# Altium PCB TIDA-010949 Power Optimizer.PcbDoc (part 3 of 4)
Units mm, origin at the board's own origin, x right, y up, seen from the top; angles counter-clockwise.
Board outline 129.4 x 84 mm, 4 copper layers (Power1, Ground1, Ground2, Power2), stack 1.926 mm thick; 265 components, 128 nets, 802 pads, 1069 vias.
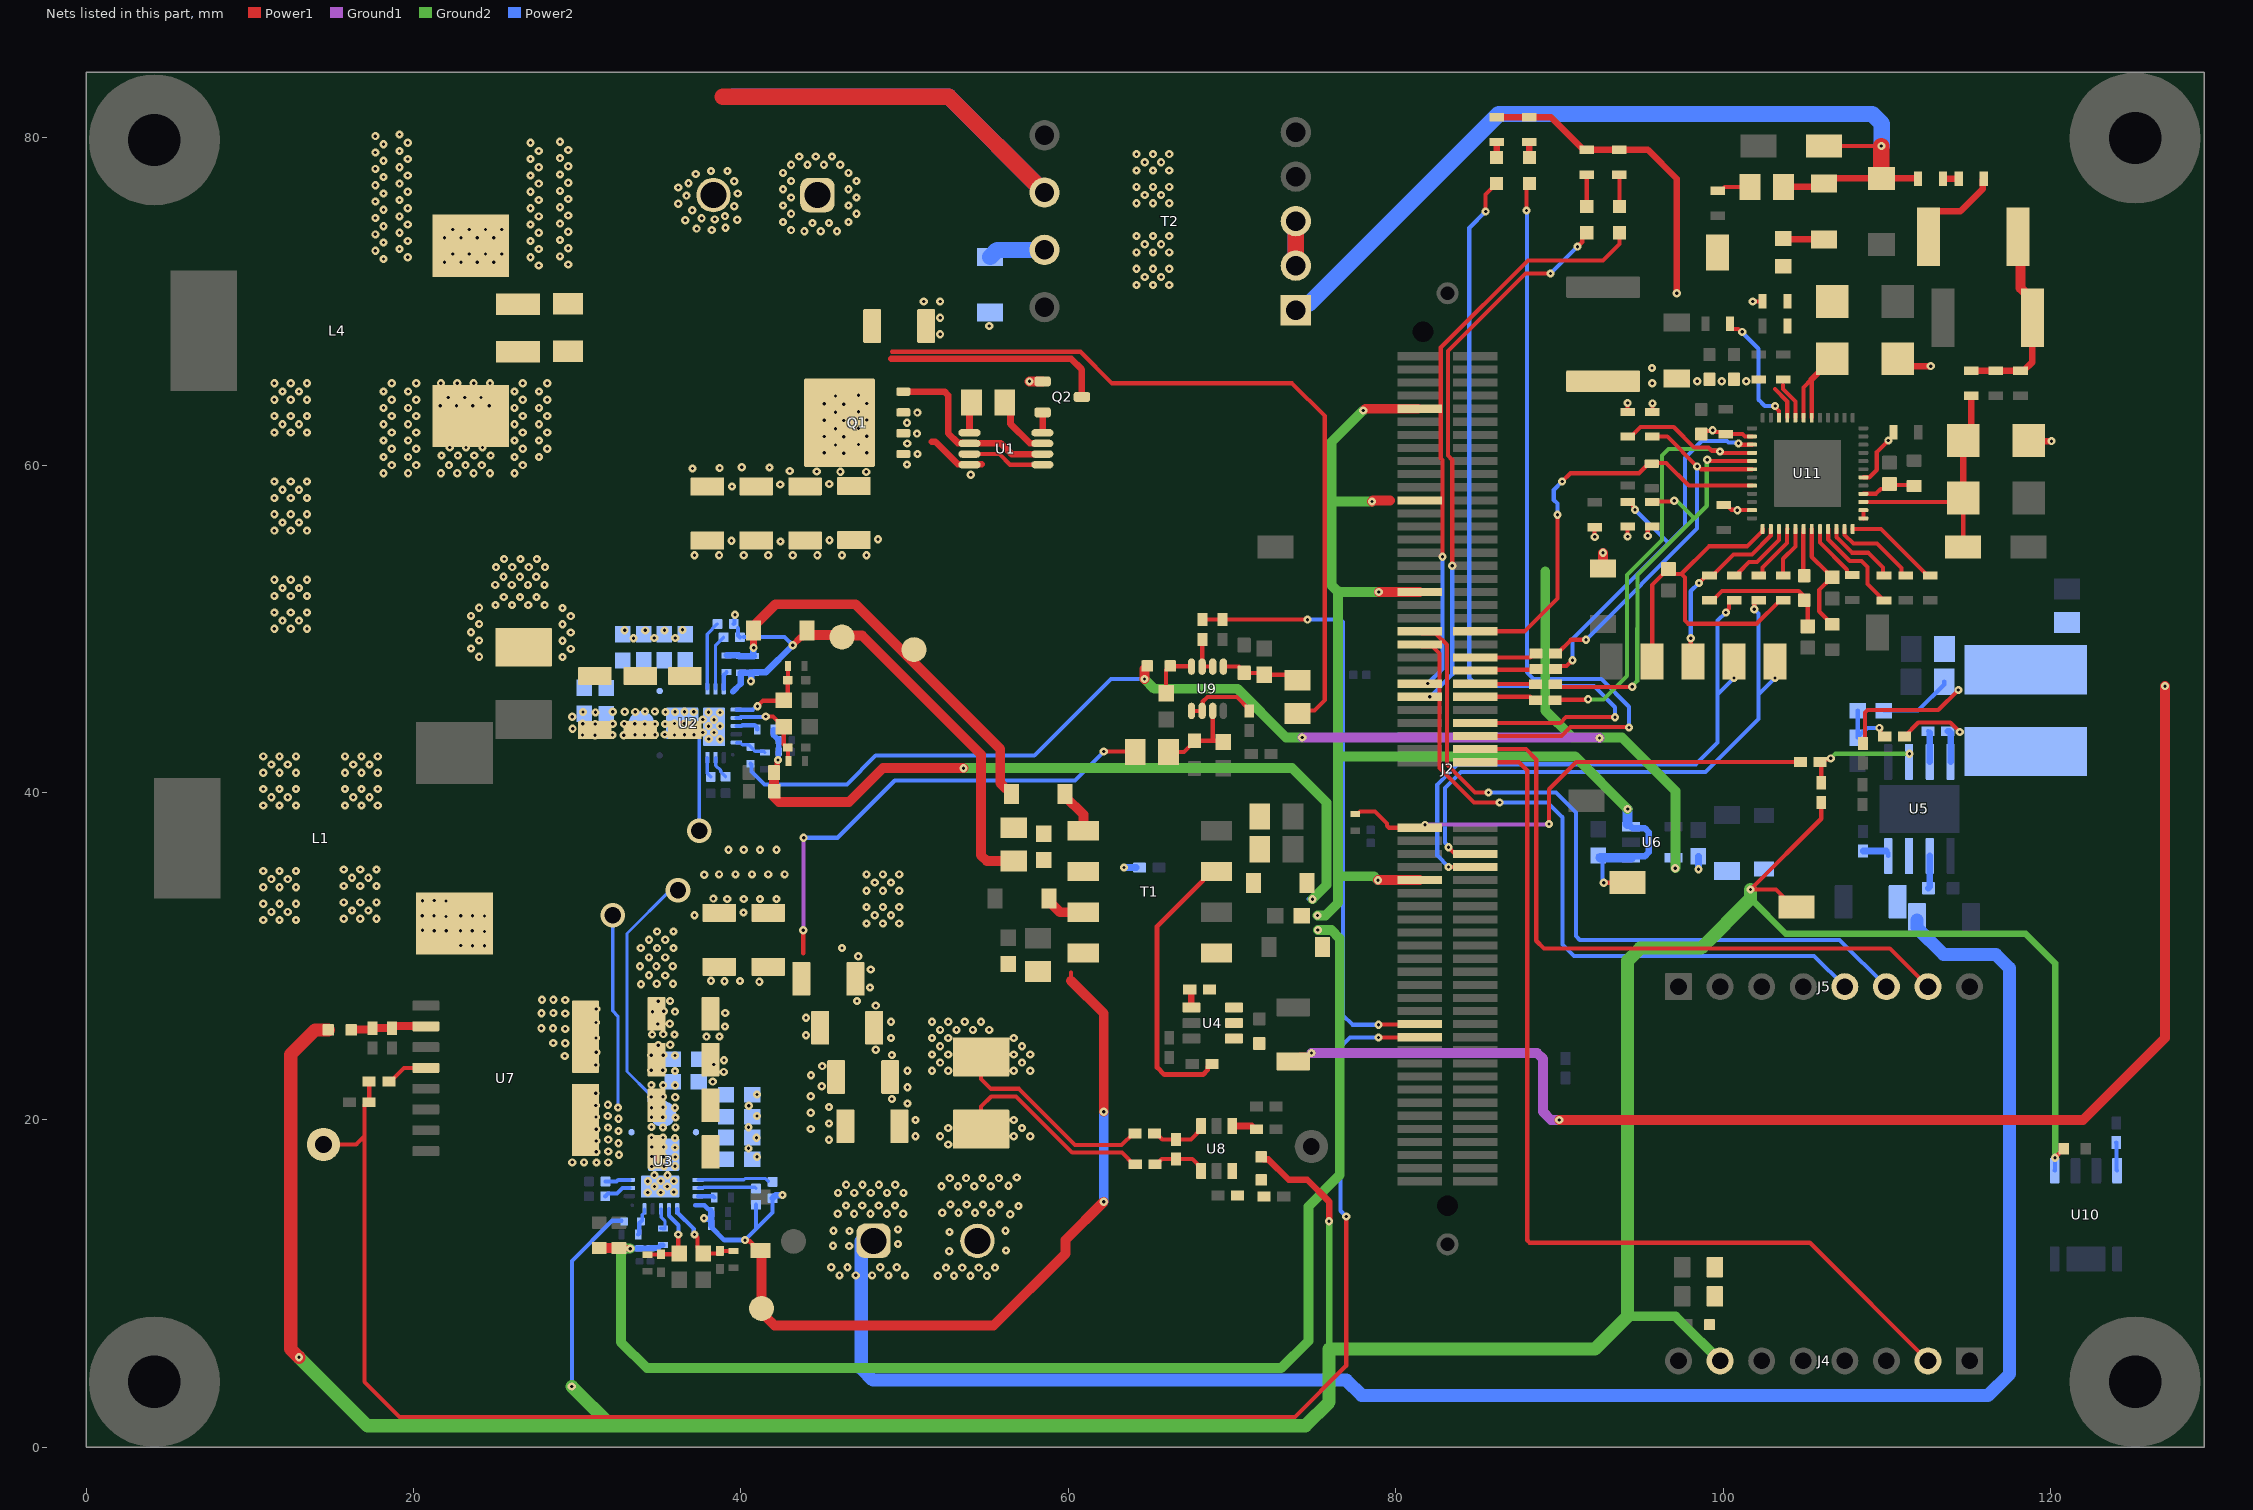
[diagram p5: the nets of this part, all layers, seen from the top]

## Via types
v1: diameter 0.5, hole 0.2, Power1 to Power2, tented both sides, 1061 vias
v2: diameter 1.5/1.5/1.5/1.5 (per signal layer), hole 1, Power1 to Power2, 4 vias
v3: diameter 3.508, hole 3.1, Power1 to Power2, tented both sides, 4 vias

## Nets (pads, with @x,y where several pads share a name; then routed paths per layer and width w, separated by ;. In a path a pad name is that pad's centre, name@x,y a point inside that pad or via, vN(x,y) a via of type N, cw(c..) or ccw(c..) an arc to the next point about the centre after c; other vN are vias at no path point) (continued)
ISO1_GND: C31.2 C44.1 C79.2 D2.2 pad.3 R16.1 R69.1 R71.1 T1.5 U3.11 | length 55.1
  Power1 w0.254: 60.174,28.5 60.174,29
  Power1 w0.3: v1@40.246,12.626 40.258,12.614 40.514,12.614 40.734,12.395 40.734,12.337 41.041,12.029 D2.2@41.194,12.029
  Power1 w0.6: D2.2@41.194,12.029 41.255,11.968 pad.3@41.255,8.498 ; pad.3@41.267,8.486 41.267,8.236 41.868,7.635 41.868,7.621 42.054,7.436 55.436,7.436 59.825,11.825 59.825,12.655 v1@62.17,15 ; 60.174,28.5 62.174,26.5 v1(62.174,20.5)
  Power2 w0.254: v1(37.749,13.987) v1@37.775,14.014 ; C31.2@38.015,14.541 38.129,14.541 38.192,14.478 C31.2@38.192,14.364 ; C79.2@38.192,13.455 C79.2@38.192,13.569 ; v1(40.246,12.654) 40.926,13.334 ; R71.1@40.926,14.816 40.926,13.334 ; R69.1@41.946,15.205 R69.1@41.937,15.214 41.937,14.345 40.926,13.334
  Power2 w0.3: U3.11@37.213,14.789 37.767,14.789 C31.2@38.015,14.541 ; C79.2@38.192,13.455 38.994,12.654 v1(40.246,12.654)
  Power2 w0.4: v1@37.775,13.961 38.192,13.961 ; C79.2@38.192,13.569 38.192,13.961 ; C31.2@38.192,14.364 38.192,13.961 ; R69.1@41.946,15.205 41.946,15.222 42.121,15.398 42.518,15.398 v1(42.539,15.418)
  Power2 w0.6: v1(62.174,15) v1(62.174,20.5)
ISO2_5V: C30.1 C45.2 C78.1 D1.1 D3.1 pad.5 R4.1 R17.2 | length 26
  Power1 w0.4: D3.1@40.728,49.914 40.771,49.871 40.771,48.853 v1(40.781,48.843)
  Power1 w0.6: D3.1@40.761,49.904 40.919,50.061 40.919,50.309 42.11,51.5 47,51.5 55.845,42.655 55.845,40.579 56.197,40.228 56.379,40.228 56.536,40.07 D1.1@56.536,39.918
  Power2 w0.254: C78.1@40.722,48.399 40.786,48.335 C78.1@40.794,48.335
  Power2 w0.4: R4.1@39.131,48.376 39.864,48.376 39.905,48.335 C30.1@40.001,48.335 C78.1@40.786,48.335 ; C78.1@40.722,48.399 40.76,48.437 40.76,48.823 v1(40.781,48.843)
ISO2_GND: C30.2 C45.1 C78.2 D3.2 pad.4 R17.1 R68.1 R70.1 T1.7 U2.11 | length 33.6
  Power1 w0.4: v1(43.174,49) 43.667,49.494 43.779,49.494 D3.2@44.036,49.751
  Power1 w0.6: D3.2@44.036,49.904 44.036,49.777 44.194,49.62 46.174,49.62 46.205,49.588 47.412,49.588 54.674,42.326 54.674,36.164 55.025,35.813 C45.1@56.675,35.813
  Power2 w0.254: R68.1@39.568,50.297 39.606,50.334 39.606,50.818 v1(39.643,50.855) ; R68.1@39.833,50.032 39.833,49.592 R70.1@39.942,49.483 ; R70.1@40.174,49.5 42.674,49.5 v1(43.174,49) ; v1(40.611,46.802) v1@40.66,46.85 ; C78.2@40.794,47.319 C78.2@40.81,47.335
  Power2 w0.35: U2.11@39.503,46.16 40.001,46.658
  Power2 w0.4: 40.001,46.658 C30.2@40.001,47.319 C78.2@40.794,47.319 40.741,47.319 40.731,47.31 40.731,47.256 40.632,47.157 40.632,46.834 v1@40.605,46.808 ; C78.2@40.81,47.335 41.509,47.335 v1(43.174,49)
LED1_EN: D15.1 J2.68 | length 34.1
  Power1 w0.254: J2.68@81.474,45.85 81.477,45.847 82.089,45.847 v1(82.093,45.843) ; v1(83.456,53.857) 83.456,60.332 83.19,60.597 83.19,66.97 87.925,71.705 v1(89.468,71.705) ; v1(91.113,73.35) 91.403,73.64 91.403,73.929 D15.1@91.674,74.2
  Power2 w0.254: v1(82.093,45.843) 83.456,47.206 v1(83.456,53.857) ; v1(89.468,71.705) v1(91.113,73.35) v1@91.124,73.35
LED2_EN: D16.1 J2.70 | length 35.7
  Power1 w0.254: J2.70@81.474,46.65 81.954,46.65 v1(81.964,46.66) ; v1(82.858,54.401) 82.858,60.315 82.756,60.417 82.756,67.178 88.078,72.5 92.674,72.5 93.674,73.5 D16.1@93.674,74.2
  Power2 w0.254: v1(81.964,46.66) 82.858,47.554 v1(82.858,54.401)
NetC1_1: C1.1 U1.7 | length 3.9
  Power1 w0.4: C1.1@56.125,63.825 56.473,63.476 56.473,62.52 57.657,61.337 58.407,61.337 U1.7@58.417,61.327
NetC1_2: C1.2 U1.1 | length 1.9
  Power1 w0.254: C1.2@53.967,63.699 C1.2@54.093,63.825
  Power1 w0.4: U1.1@53.967,61.977 C1.2@53.967,63.699
NetC32_2: C32.2 R8.1 R10.2 U2.12 | length 5.3
  Power1 w0.254: v1(41.019,45.268) 41.36,45.61 42.59,45.61 R10.2@42.615,45.635 42.865,45.885 C32.2@42.865,46.86 42.87,46.865 42.87,47.731 R8.1@42.874,47.735
  Power2 w0.254: U2.12@39.728,45.06 40.742,45.06 40.95,45.268 v1(41.019,45.268)
NetC33_2: C33.2 R9.1 R11.2 U3.12 | length 5.3
  Power1 w0.254: v1(37.174,13) 37.352,12.821 37.352,12.187 R11.2@37.7,11.839 38.723,11.839 38.723,11.862 38.85,11.99 R9.1@39.536,11.99
  Power2 w0.254: U3.12@36.113,14.564 36.113,14.343 37.125,13.331 37.125,13.049 v1(37.174,13)
NetC34_2: C34.2 R12.2 R14.1 U2.13 | length 5.4
  Power1 w0.254: v1(41.524,44.643) 41.972,44.643 42.242,44.373 42.242,44.358 42.59,44.01 R12.2@42.615,44.01 42.615,42.947 42.815,42.747 C34.2@42.865,42.747 42.886,42.726 42.886,41.956 R14.1@42.907,41.935
  Power2 w0.254: U2.13@39.728,44.56 39.949,44.56 39.995,44.606 41.487,44.606 v1(41.524,44.643)
NetC35_2: C35.2 R13.2 R15.1 U3.13 | length 5
  Power1 w0.254: R15.1@34.283,11.766 34.294,11.777 35.109,11.777 C35.2@35.12,11.789 36.175,11.789 R13.2@36.225,11.839 36.174,11.89 v1(36.174,13)
  Power2 w0.254: U3.13@35.613,14.564 35.615,14.562 35.615,14.146 36.195,13.566 36.195,13.021 v1(36.174,13)
NetC46_1: C46.1 T1.4 U4.6
NetC46_2: C46.2 U4.1 | length 1.1
  Power1 w0.254: C46.2@67.424,27.968 C46.2@67.524,27.868
  Power1 w0.4: U4.1@67.524,26.868 C46.2@67.524,27.868
NetC49_2: C49.2 C52.2 R18.2 | length 3.9
  Power1 w0.254: v1(109.552,43.95) 109.606,43.896 109.606,43.602 109.779,43.429 R18.2@109.879,43.429
  Power2 w0.254: C49.2@108.217,43.353 108.217,43.378 C49.2@108.23,43.392 ; C52.2@108.23,45.002 C49.2@108.23,43.392 ; v1(109.552,43.95) 108.813,43.95 108.59,43.726 108.565,43.726 C49.2@108.23,43.392
NetC50_1: C50.1 C51.1 D5.2 R20.2 T1.2 | length 17.6
  Power1 w0.254: T1.2@68.782,35.174 T1.2@69.053,35.174
  Power1 w0.3: R20.2@68.774,23.418 68.674,23.418 68.524,23.268 68.524,23.06 68.231,22.768 65.873,22.768 65.434,23.206 65.434,31.826 68.248,34.639 68.248,34.739 68.683,35.174 T1.2@68.782,35.174
NetC53_1: C53.1 L2.1 R18.1 U5.8 | length 6
  Power1 w0.254: R18.1@111.079,43.429 111.929,44.28 113.884,44.28 v1(114.466,43.698)
  Power2 w0.4: C53.1@113.729,43.747 113.805,43.747 113.905,43.647 U5.8@113.905,41.875
NetC53_2: C53.2 U5.7 | length 1.9
  Power2 w0.254: C53.2@112.529,43.747 C53.2@112.635,43.641
  Power2 w0.4: U5.7@112.635,41.875 C53.2@112.635,43.641
NetC65_1: C65.1 C66.1 FB1.2 U7.4 | length 4.6
  Power1 w0.5: FB1.2@16.215,25.515 17.45,25.515 17.5,25.565 C65.1@17.5,25.6 ; C65.1@17.515,25.615 C66.1@18.671,25.615 ; C66.1@18.686,25.6 18.686,25.68 18.736,25.73 U7.4@20.735,25.73
NetC67_1: C67.1 C68.1 FB2.2 U8.6
NetC71_1: C71.1 R34.2 U8.3 | length 3.4
  Power1 w0.254: R34.2@65.279,19.178 65.379,19.178 65.745,18.813 C71.1@66.584,18.813 67.499,18.813 68.114,19.427 U8.3@68.114,19.627
NetC71_2: C71.2 R37.2 U8.4 | length 3.4
  Power1 w0.254: R37.2@65.294,17.293 65.394,17.293 65.714,17.613 C71.2@66.584,17.613 67.579,17.613 68.114,17.077 U8.4@68.114,16.877
NetC73_1: C73.1 R40.1 R43.2 U9.3 | length 5.5
  Power1 w0.254: R40.1@66.129,42.48 67.077,42.48 67.711,43.114 R43.2@67.711,43.164 68.754,43.164 ; U9.3@68.829,44.989 68.829,43.239 68.754,43.164 ; C73.1@69.479,43.09 69.405,43.164 68.754,43.164
NetC75_1: C75.1 R41.1 R45.2 U9.5 | length 4.9
  Power1 w0.254: U9.5@69.479,47.689 70.422,47.689 70.749,47.362 R45.2@70.749,47.312 71.862,47.312 C75.1@71.974,47.2 73.659,47.2 R41.1@74.004,46.855
NetC77_2: C77.2 FB3.2 U9.8 | length 3.1
  Power1 w0.254: C77.2@65.982,46.062 65.982,47.482 66.116,47.615 FB3.2@66.316,47.615 ; FB3.2@66.232,47.731 66.253,47.71 67.507,47.71 U9.8@67.529,47.689
NetC81_1: C81.1 D10.2 R56.2 R58.2 T2.1 TP26.1 | length 56.3
  Power1 w0.254: C81.1@105.974,77 C81.1@106.174,77.2 C81.1@106.489,77.515 ; TP26.1@106.174,79.5 v1(109.674,79.5) ; R58.2@111.897,77.515 R58.2@111.912,77.5
  Power1 w0.4: R56.2@103.69,77 C81.1@105.974,77 ; C81.1@106.489,77.515 D10.2@109.674,77.515 110.174,77.515 R58.2@111.897,77.515
  Power1 w1: D10.2@109.674,77.515 v1(109.674,79.5)
  Power2 w1: T2.1@73.902,69.463 74.327,69.888 74.735,69.888 86.298,81.451 109.112,81.451 109.698,80.865 v1@109.698,79.525
NetC81_2: C81.2 L3.2 | length 2.5
  Power1 w0.254: L3.2@103.674,73.85 L3.2@103.724,73.8
  Power1 w0.4: L3.2@103.724,73.8 C81.2@106.174,73.8
NetC82_2: C82.2 C83.2 R51.1 | length 8.1
  Power1 w0.254: R51.1@99.174,51.738 99.364,51.738 99.945,52.319 104.63,52.319 105.174,51.775 105.174,51.75 C83.2@105.174,50.15
NetC84_2: C84.2 T2.8 | length 3.5
  Power2 w1: C84.2@55.229,72.72 55.652,73.143 58.541,73.143 T2.8@58.552,73.153
NetC85_1: C85.1 U11.22 | length 4.6
  Power1 w0.254: U11.22@106.924,56.1 106.931,56.093 106.931,55.598 107.876,54.652 108.869,54.652 109.778,53.743 109.778,53.316 C85.1@109.837,53.257
NetC85_2: C85.2 U11.21 | length 6.2
  Power1 w0.254: U11.21@106.424,56.1 106.431,56.093 106.431,55.456 107.744,54.143 108.454,54.143 108.821,53.776 108.821,52.749 C85.2@109.837,51.733
NetC86_1: C86.1 C91.1 L5.1 L6.2 R59.2 | length 12.1
  Power1 w0.254: C91.1@118.174,65.762 C91.1@118.364,65.762
  Power1 w0.4: C86.1@115.174,65.762 R59.2@116.674,65.762 C91.1@118.174,65.762 ; C91.1@118.364,65.762 118.904,66.302 L6.2@118.904,69
  Power1 w0.6: L5.1@118.174,74.108 118.174,70.81 118.904,70.08 L6.2@118.904,69
NetC86_2: C86.2 D13.2 D14.1 TP28.1 U11.27 | length 15.6
  Power1 w0.254: U11.27@108.574,57.75 114.424,57.75 D14.1@114.674,58 TP28.1@114.674,55 ; D13.2@114.674,61.5 D13.2@115.174,62
  Power1 w0.4: D14.1@114.674,58 D13.2@114.674,61.5 ; D13.2@115.174,62 C86.2@115.174,64.238
NetC87_1: C87.1 R58.1 | length 1
  Power1 w0.4: R58.1@113.436,77.5 C87.1@114.412,77.5
NetC87_2: C87.2 L5.2 | length 5.7
  Power1 w0.4: L5.2@112.674,74.643 112.674,75.122 113.061,75.51 114.501,75.51 115.882,76.89 115.882,77.446 C87.2@115.936,77.5
  Power1 w0.6: L5.2@112.561,73.961 L5.2@112.561,74.643
NetC88_1: C88.1 R56.1 | length 2.1
  Power1 w0.254: C88.1@99.674,76.762 99.864,76.762 100.102,77 R56.1@101.658,77
NetC89_1: C89.1 U11.23 | length 5.3
  Power1 w0.254: U11.23@107.424,56.1 107.431,56.093 107.431,55.74 107.962,55.208 109.399,55.208 110.895,53.713 110.895,53.389 111.022,53.262 C89.1@111.174,53.262
NetC90_1: C90.1 U11.24 | length 5.9
  Power1 w0.254: U11.24@107.924,56.1 109.645,56.1 112.483,53.262 C90.1@112.674,53.262
NetC92_2: C92.2 C93.2 U11.19 | length 7
  Power1 w0.254: U11.19@105.424,56.1 105.424,54.4 106.351,53.473 106.351,53.448 C93.2@106.649,53.15 ; C92.2@106.674,50.275 105.876,51.073 105.876,52.377 C93.2@106.649,53.15 ; C93.2@106.674,53.15 C93.2@106.649,53.15
NetC94_2: C94.2 C95.2 U11.28 | length 3.4
  Power1 w0.254: U11.28@108.574,58.25 108.581,58.257 109.341,58.257 109.636,58.552 109.876,58.552 C95.2@110.174,58.85 110.236,58.787 111.611,58.787 C94.2@111.674,58.725
NetD1_2: D1.2 T1.8 | length 2.7
  Power1 w0.254: D1.2@59.811,39.765 D1.2@59.811,39.918
  Power1 w0.6: D1.2@59.811,39.765 60.923,38.654 T1.8@60.923,37.664
NetD4_2: D4.2 T1.6 | length 2.5
  Power1 w0.6: D4.2@58.811,33.518 58.811,33.365 59.493,32.684 T1.6@60.923,32.684
NetD7_1: D7.1 J2.63 | length 49.8
  Power1 w0.254: J2.63@84.874,44.25 90.06,44.25 90.415,44.604 v1(93.404,44.604) ; v1(85.5,75.5) 85.5,76.526 D7.1@86.174,77.2
  Power2 w0.254: v1(85.5,75.5) 84.496,74.496 84.496,47.001 84.998,46.5 92.116,46.5 93.404,45.211 v1(93.404,44.604)
NetD7_2: D7.2 R29.1 | length 0.9
  Power1 w0.4: D7.2@86.174,78.8 R29.1@86.174,79.738
NetD9_2: D9.2 D11.1 L3.1 R50.1 R52.2 TP25.1 U11.42 U11.43 | length 6.7
  Power1 w0.254: U11.43@104.924,62.9 104.924,64.75 105.424,65.25 U11.42@105.424,62.9
  Power1 w0.4: 105.424,65.25 D9.2@106.674,66.5
NetD12_1: D12.1 J2.61 | length 47.9
  Power1 w0.254: J2.61@84.874,43.45 90.144,43.45 90.694,44 94.229,44 v1(94.258,43.971) ; v1(87.993,75.562) 87.993,77.019 D12.1@88.174,77.2
  Power2 w0.254: v1(87.993,75.562) 88.016,75.538 88.016,47.346 88.428,46.934 92.566,46.934 94.258,45.242 v1(94.258,43.971)
NetD12_2: D12.2 R76.1 | length 0.9
  Power1 w0.4: D12.2@88.174,78.8 R76.1@88.174,79.738
NetD15_2: D15.2 R61.1 | length 1.9
  Power1 w0.254: D15.2@91.674,75.8 R61.1@91.674,77.738
NetD16_2: D16.2 R62.1 | length 1.9
  Power1 w0.254: D16.2@93.674,75.8 R62.1@93.674,77.738
NetJ2_67: J2.67 R24.2 | length 3.7
  Power1 w0.254: J2.67@84.874,45.85 88.22,45.85 88.434,45.636 R24.2@88.534,45.636
NetJ2_69: J2.69 R26.2 | length 3.7
  Power1 w0.254: J2.69@84.874,46.65 84.889,46.635 88.534,46.635 R26.2@88.549,46.619
NetJ2_71: J2.71 R27.2 | length 3.7
  Power1 w0.254: J2.71@84.874,47.45 84.924,47.501 88.519,47.501 R27.2@88.57,47.552
NetJ2_73: J2.73 R28.2 | length 3.8
  Power1 w0.254: J2.73@84.874,48.25 88.223,48.25 88.474,48.5 R28.2@88.574,48.5
NetQ1_4: Q1.4 U1.2 U1.6 | length 11.4
  Power1 w0.4: Q1.4@49.923,64.492 52.439,64.492 52.674,64.257 52.674,61.936 53.258,61.352 53.478,61.352 53.494,61.337 53.957,61.337 U1.2@53.967,61.327 55.885,61.327 56.535,60.677 U1.6@58.417,60.677
NetQ2_2: Q2.2 U1.8 | length 1.2
  Power1 w0.4: U1.8@58.417,61.977 58.434,61.994 Q2.2@58.434,63.218
NetR3_2: R3.2 U3.10 | length 1
  Power2 w0.254: U3.10@37.388,15.339 38.306,15.339 R3.2@38.378,15.267
NetR4_2: R4.2 U2.10 | length 1.1
  Power2 w0.254: U2.10@38.953,46.335 38.953,47.165 R4.2@39.131,47.343
NetR5_2: R5.2 U2.14 | length 1.5
  Power2 w0.254: U2.14@39.728,44.06 39.73,44.062 40.056,44.062 40.103,44.109 40.847,44.109 40.999,43.957 R5.2@40.999,43.843
NetR7_2: R7.2 U3.14 | length 1.6
  Power2 w0.2: R7.2@35.085,13.388 35.289,13.388 35.358,13.457 35.358,13.827 35.132,14.053 35.132,14.544 U3.14@35.113,14.564
  Power2 w0.254: R7.2@35.229,13.367 R7.2@35.344,13.367
NetR19_1: R19.1 R22.1 U5.6 | length 6.9
  Power1 w0.254: R19.1@105.937,41.86 106.11,42.033 106.464,42.033 106.518,42.087 v1(106.587,42.087) ; R22.1@106,40.6 R19.1@106,41.86
  Ground2 w0.254: v1(106.587,42.087) 106.873,42.373 v1(111.387,42.373)
NetR30_1: R30.1 U11.15 | length 4.4
  Power1 w0.254: R30.1@100.674,53.262 100.864,53.262 100.991,53.389 100.991,53.484 101.594,54.088 102.07,54.088 103.417,55.434 103.417,56.093 U11.15@103.424,56.1
NetR31_1: R31.1 U7.6 | length 2.6
  Power1 w0.254: R31.1@18.494,22.339 18.594,22.339 19.43,23.175 U7.6@20.75,23.175
NetR32_1: R32.1 U8.1 | length 1.6
  Power1 w0.4: U8.1@70.014,19.627 71.208,19.627 71.403,19.432 R32.1@71.503,19.432
NetR33_2: R33.2 U5.4 | length 1.8
  Power2 w0.254: U5.4@109.972,36.427 110.095,36.304 U5.4@110.095,36.125
  Power2 w0.4: R33.2@108.562,36.427 U5.4@109.972,36.427
NetR38_1: R38.1 U11.16 | length 3.6
  Power1 w0.254: R38.1@102.174,53.262 102.285,53.262 102.412,53.389 102.412,53.748 103.917,55.252 103.917,56.093 U11.16@103.924,56.1
NetR39_1: R39.1 U11.17 | length 3.1
  Power1 w0.254: R39.1@103.674,53.262 103.674,54.283 104.424,55.033 U11.17@104.424,56.1
NetR42_1: R42.1 U9.1 U9.2 | length 4.6
  Power1 w0.254: U9.1@67.529,44.989 U9.2@68.179,44.989 68.216,45.026 68.216,45.552 68.504,45.839 70.302,45.839 71.054,45.087 R42.1@71.054,44.987
NetR44_1: R44.1 U9.6 U9.7 | length 2.3
  Power1 w0.254: R44.1@68.204,49.36 68.191,49.348 68.191,47.701 U9.7@68.179,47.689 U9.6@68.829,47.689
NetR57_1: R57.1 U11.20 | length 3.7
  Power1 w0.254: U11.20@105.924,56.1 105.924,55.268 107.583,53.609 107.583,53.418 107.71,53.291 R57.1@107.9,53.291
NetR60_2: R60.2 U11.46 | length 7.6
  Power1 w0.254: R60.2@100.424,68.643 100.424,68.443 100.547,68.32 100.928,68.32 101.105,68.143 v1(101.174,68.143) ; v1(103.186,63.616) 103.186,63.547 103.417,63.316 103.417,62.907 U11.46@103.424,62.9
  Power2 w0.254: v1(101.174,68.143) 101.174,68.111 102.174,67.111 102.174,64 102.551,63.623 103.179,63.623 v1(103.186,63.616)
NetR63_2: R63.2 U10.4 | length 1.7
  Power2 w0.254: R63.2@124.02,18.611 124.049,18.582 124.049,16.929 U10.4@124.079,16.9
NetR64_2: R64.2 U2.3 | length 1.4
  Power2 w0.2: U2.3@38.453,42.135 38.47,42.117 38.47,41.644 38.764,41.35 38.764,41.267 R64.2@39.066,40.965
NetR65_2: R65.2 U3.3 | length 1.7
  Power2 w0.254: R65.2@31.718,15.339 31.88,15.5 32.441,15.5 32.778,15.837 33.186,15.837 U3.3@33.188,15.839
NetR66_2: R66.2 U2.4 | length 1.3
  Power2 w0.2: U2.4@37.953,42.135 37.953,41.168 R66.2@38.164,40.956
NetR67_2: R67.2 U3.4 | length 1.5
  Power2 w0.254: R67.2@31.727,16.235 32.408,16.235 32.509,16.337 33.186,16.337 U3.4@33.188,16.339
NetR68_2: R68.2 U2.8 | length 4.2
  Power2 w0.2: U2.8@37.953,46.335 37.953,49.681 R68.2@38.568,50.297
NetR69_2: R69.2 U3.8 | length 4.4
  Power2 w0.2: U3.8@37.397,16.348 40.187,16.348 40.255,16.416 41.51,16.416 R69.2@41.694,16.231
NetR70_2: R70.2 U2.9 | length 3.4
  Power2 w0.2: U2.9@38.453,46.335 38.453,48.994 R70.2@38.942,49.483
NetR71_2: R71.2 U3.9 | length 3.6
  Power2 w0.2: U3.9@37.388,15.839 37.413,15.864 37.717,15.864 37.736,15.882 40.859,15.882 R71.2@40.926,15.816
NetR72_1: R72.1 R73.2 U2.16 | length 2
  Power2 w0.2: U2.16@39.728,43.06 39.753,43.035 39.978,43.035 40.093,42.919 40.468,42.919 40.743,42.644 40.743,42.638 40.86,42.521 41.395,42.521 R73.2@41.474,42.443
NetR74_1: R74.1 R75.2 U3.16 | length 1.7
  Power2 w0.2: R74.1@33.975,13.832 33.975,14.201 34.113,14.339 U3.16@34.113,14.564
  Power2 w0.254: R75.2@33.728,12.999 33.791,13.062 33.791,13.691 R74.1@33.895,13.794
NetT2_2: T2.2 T2.3 | length 5.4
  Power1 w1: T2.2@73.902,72.183 T2.3@73.902,74.903
  Power2 w1: T2.2@73.902,72.183 T2.3@73.902,74.903
NetU1_3: U1.3 U1.5 | length 4.7
  Power1 w0.254: U1.3@53.967,60.677 55.79,60.677 56.44,60.027 U1.5@58.417,60.027
NetU11_25: U11.25 U11.26 | length 0.5
  Power1 w0.254: U11.25@108.574,56.75 U11.26@108.574,57.25
Output_I: C70.1 J2.24 R31.2 TP16.1 | length 108.1
  Power1 w0.254: TP16.1@14.5,18.5 16.5,18.5 17,19 ; C70.1@17.28,21.079 17.18,21.079 17.007,20.906 17.007,20.765 17,20.757 17,19 ; C70.1@17.294,21.092 R31.2@17.294,22.339 ; v1(76.98,14.095) 76.98,4.98 73.857,1.857 19.143,1.857 17,4 17,19 ; v1(78.955,25.035) 78.963,25.043 81.466,25.043 J2.24@81.474,25.05
  Power2 w0.254: v1(76.98,14.095) 76.625,14.45 76.625,24.451 77.209,25.035 v1(78.955,25.035)
Output_V: C76.1 J2.26 R44.2 | length 37.6
  Power1 w0.254: R44.2@68.204,50.56 C76.1@69.426,50.56 ; C76.1@69.427,50.561 v1(74.612,50.561) ; v1(78.948,25.816) 78.965,25.833 81.457,25.833 J2.26@81.474,25.85
  Power2 w0.254: v1(74.612,50.561) 76.635,50.561 76.784,50.412 76.784,26.39 77.357,25.816 v1(78.948,25.816)
PA_IN: C82.1 U11.18 | length 2.9
  Power1 w0.254: U11.18@104.924,56.1 104.917,56.093 104.917,55.872 104.907,55.862 104.907,53.3 C82.1@104.962,53.246
PGND: C2.1 C3.1 C4.1 C5.1 C6.1 C7.1 C8.1 C9.1 C10.1 C11.1 C12.1 C13.1 C14.1 C15.1 C16.1 C17.1 C18.1 C19.1 C20.1 C21.1 C22.1 C23.1 C24.1 C25.1 C26.1 C27.1 C28.1 C29.1 C60.1 C61.1 C69.1 C84.1 L4.1 Q1.1 Q1.2 Q1.3 Q2.1 R1.2 R2.2 R23.2 R34.1 U1.4 U2.6 U3.6 | length 38.8
  Power1 w0.254: R2.2@54.674,23.853 54.674,22.5 55.275,21.899 56.986,21.899 60.422,18.462 63.263,18.462 63.979,19.178 R34.1@64.079,19.178
  Power1 w0.4: 51.647,61.426 51.884,61.426 53.258,60.052 53.478,60.052 53.503,60.027 U1.4@53.967,60.027 ; U1.4@53.986,60.046 54.699,60.046
  Power1 w0.6: v1(57.63,65.118) Q2.1@58.434,65.118
  Power2 w0.2: v1@34.437,21.565 33.043,22.958 33.043,31.389 35.69,34.035 v2(36.159,34.035) ; v2(37.462,37.662) 37.462,43.5
  Power2 w0.254: 34.437,21.153 34.437,21.395 v1@34.437,21.565
  Power2 w0.4: v1(63.405,35.419) R1.2@64.155,35.419
  other v1: 34.31,15.569 35.108,15.569 35.907,15.59 35.501,15.93 34.727,15.938 34.318,16.253 35.905,16.26 35.11,16.274 34.714,16.625 35.518,16.621 34.554,17.155 35.298,17.163 35.981,17.168 35.269,17.754 35.984,17.741 40.99,17.754 34.555,17.768 40.466,18.263 35.979,18.313 35.274,18.341 34.55,18.345 35.975,18.895 35.237,18.927 40.96,18.908 34.546,18.931 50.674,19 34.541,19.564 35.242,19.541 36.007,19.545 40.471,19.554 50.674,20 36.007,20.145 34.537,20.168 35.233,20.168 40.983,20.232 34.541,20.736 35.979,20.745 35.248,20.766 40.48,20.868 50.174,21 49.225,21.272 35.988,21.384 34.53,21.395 35.248,21.42 40.983,21.551 50.174,22 35.251,22.123 35.984,22.115 34.532,22.139 35.977,22.991 50.174,23 51.674,23 52.674,23 56.674,23 57.674,23 34.52,23.035 35.233,23.03 52.174,23.5 57.174,23.5 34.53,23.948 35.253,23.958 35.974,23.934 49.225,23.972 51.674,24 52.674,24 56.674,24 57.674,24 48.244,24.282 52.174,24.5 57.174,24.5 34.952,24.569 35.683,24.588 49.174,25 51.674,25 52.674,25 56.674,25 34.58,25.221 35.949,25.221 35.263,25.24 52.174,25.5 53.174,25.5 54.174,25.5 55.174,25.5 34.927,25.856 35.658,25.875 49.174,26 51.674,26 52.674,26 53.674,26 54.674,26 34.601,26.615 35.97,26.615 35.284,26.634 48.244,26.982 34.947,27.25 35.679,27.27 47.095,27.266 47.889,28.092 33.9,28.287 34.861,28.318 35.861,28.318 35.381,28.82 34.382,28.839 47.934,29.193 33.839,29.384 34.839,29.384 35.839,29.384 34.386,29.929 35.386,29.929 47.174,30 33.886,30.504 34.886,30.504 35.886,30.504 46.174,30.5 34.386,31.004 35.386,31.004 34.886,31.504 35.886,31.504 47.674,32 48.674,32 49.674,32 10.818,32.21 11.818,32.21 12.818,32.21 15.744,32.291 16.744,32.291 17.744,32.291 37.174,32.5 48.174,32.5 49.174,32.5 40.167,32.674 11.318,32.71 12.318,32.71 16.244,32.791 17.244,32.791 47.674,33 48.674,33 49.674,33 10.818,33.21 11.818,33.21 12.818,33.21 15.744,33.291 16.744,33.291 17.744,33.291 39.174,33.5 40.174,33.5 41.174,33.5 42.174,33.5 38.32,33.517 47.674,34 48.674,34 49.674,34 10.818,34.21 11.818,34.21 12.818,34.21 15.744,34.291 16.744,34.291 17.744,34.291 48.174,34.5 49.174,34.5 11.318,34.71 12.318,34.71 16.244,34.791 17.244,34.791 37.764,34.972 38.674,35 39.674,35 40.674,35 41.674,35 42.674,35 47.674,35 48.674,35 49.674,35 10.818,35.21 11.818,35.21 12.818,35.21 15.744,35.291 16.744,35.291 17.744,35.291 40.174,36.5 41.174,36.5 42.174,36.5 39.248,36.507 10.818,39.21 11.818,39.21 12.818,39.21 15.818,39.21 16.818,39.21 17.818,39.21 11.318,39.71 12.318,39.71 16.318,39.71 17.318,39.71 10.818,40.21 11.818,40.21 12.818,40.21 15.818,40.21 16.818,40.21 17.818,40.21 10.818,41.21 11.818,41.21 12.818,41.21 15.818,41.21 16.818,41.21 17.818,41.21 11.318,41.71 12.318,41.71 16.318,41.71 17.318,41.71 10.818,42.21 11.818,42.21 12.818,42.21 15.818,42.21 16.818,42.21 17.818,42.21 38.722,43.258 38.039,43.265 31.093,43.499 32.152,43.508 32.84,43.503 34.109,43.515 30.328,43.52 33.533,43.529 34.753,43.525 35.349,43.54 35.939,43.519 36.55,43.522 37.132,43.529 37.666,43.661 38.353,43.674 29.722,43.899 38.017,44.057 38.722,44.056 30.333,44.2 31.109,44.181 32.169,44.198 32.871,44.195 33.525,44.195 34.123,44.18 34.751,44.189 35.364,44.185 35.951,44.221 36.537,44.217 37.128,44.245 38.362,44.448 37.67,44.465 29.703,44.63 31.118,44.898 38.024,44.907 38.724,44.889 30.357,44.921 32.177,44.931 32.907,44.935 33.546,44.927 35.396,44.922 35.978,44.927 36.551,44.931 37.124,44.928 34.146,44.954 34.746,44.954 33.44,49.42 34.708,49.447 35.989,49.436 32.898,49.916 34.154,49.906 35.33,49.906 36.437,49.937 11.5,50 12.5,50 13.5,50 12,50.5 13,50.5 11.5,51 12.5,51 13.5,51 11.5,52 12.5,52 13.5,52 12,52.5 13,52.5 11.5,53 12.5,53 13.5,53 37.174,54.5 38.674,54.5 40.174,54.5 41.674,54.5 43.174,54.5 44.674,54.5 46.174,54.5 47.674,54.5 42.416,55.34 39.433,55.383 45.413,55.412 48.381,55.47 11.5,56 12.5,56 13.5,56 12,56.5 13,56.5 11.5,57 12.5,57 13.5,57 11.5,58 12.5,58 13.5,58 12,58.5 13,58.5 11.5,59 12.5,59 13.5,59 54.039,59.414 18.174,59.5 19.674,59.5 21.674,59.5 22.674,59.5 23.674,59.5 24.674,59.5 26.174,59.5 18.674,60 20.174,60 22.174,60 23.174,60 24.174,60 26.674,60 50.153,60.037 18.174,60.5 19.674,60.5 26.174,60.5 27.674,60.5 21.712,60.585 22.712,60.585 23.712,60.585 24.712,60.585 50.792,60.675 18.674,61 20.174,61 26.674,61 28.174,61 22.212,61.085 23.212,61.085 24.212,61.085 50.162,61.316 18.174,61.5 19.674,61.5 26.174,61.5 27.674,61.5 50.762,61.926 11.5,62 12.5,62 13.5,62 18.674,62 20.174,62 26.674,62 28.174,62 12,62.5 13,62.5 18.174,62.5 19.674,62.5 26.174,62.5 27.674,62.5 50.153,62.587 11.5,63 12.5,63 13.5,63 18.674,63 20.174,63 26.674,63 28.174,63 50.782,63.207 18.174,63.5 19.674,63.5 26.174,63.5 27.674,63.5 21.627,63.629 22.627,63.629 23.627,63.629 24.627,63.629 11.5,64 12.5,64 13.5,64 18.674,64 20.174,64 26.674,64 28.174,64 22.127,64.129 23.127,64.129 24.127,64.129 12,64.5 13,64.5 18.174,64.5 19.674,64.5 26.174,64.5 27.674,64.5 11.5,65 12.5,65 13.5,65 18.674,65 20.174,65 21.674,65 22.674,65 23.674,65 24.674,65 26.674,65 28.174,65 52.174,68 55.174,68.5 52.174,69 51.174,70 52.174,70 64.174,71 65.174,71 66.174,71 64.674,71.5 65.674,71.5 64.174,72 65.174,72 66.174,72 64.174,73 65.174,73 66.174,73 64.674,73.5 65.674,73.5 64.174,74 65.174,74 66.174,74 64.174,76 65.174,76 66.174,76 64.674,76.5 65.674,76.5 64.174,77 65.174,77 66.174,77 64.174,78 65.174,78 66.174,78 64.674,78.5 65.674,78.5 64.174,79 65.174,79 66.174,79
PGOOD_5V: C112.1 J2.56 R19.2 | length 30.3
  Power1 w0.254: C112.1@77.534,38.681 77.648,38.681 77.816,38.849 78.739,38.849 79.477,38.111 79.477,37.973 79.6,37.85 J2.56@81.474,37.85 J2.56@81.449,37.874 ; v1(89.373,38.071) 89.373,40.199 91.035,41.86 R19.2@104.737,41.86
  Ground1 w0.254: v1(81.797,38.024) 81.82,38.047 89.35,38.047 v1(89.373,38.071)
PLC_HRPWM1: J2.49 R30.2 TP22.1 | length 35.8
  Power1 w0.254: v1(83.237,35.457) 83.244,35.45 J2.49@84.874,35.45 ; v1(100.174,51) 100.174,51.069 100.356,51.251 100.356,51.611 100.483,51.738 R30.2@100.674,51.738
  Power2 w0.254: v1(83.237,35.457) 82.547,36.147 82.547,40.48 83.797,41.73 98.351,41.73 99.674,43.053 99.674,46 ; v1(100.174,51) 99.674,50.5 99.674,46 ; v1(100.674,47) 99.674,46
PLC_HRPWM2: J2.51 R38.2 TP23.1 | length 35.4
  Power1 w0.254: v1(83.224,36.659) 83.634,36.25 J2.51@84.874,36.25 ; v1(101.912,51.198) 101.912,51.667 101.983,51.738 R38.2@102.174,51.738
  Power2 w0.254: v1(83.224,36.659) 83.224,36.722 83.015,36.931 83.015,40.28 83.986,41.25 98.924,41.25 102.174,44.5 102.174,46 ; v1(101.912,51.198) 102.174,50.937 102.174,46 ; v1(103.174,47) 102.174,46
PV_PGND: J1.2 R2.1 R37.1 | length 12.8
  Power1 w0.254: R2.1@54.674,19.433 54.674,20.812 55.295,21.433 56.81,21.433 60.24,18.002 63.285,18.002 63.994,17.293 R37.1@64.094,17.293
  other v1: 52.027,10.476 53.027,10.476 54.027,10.476 55.027,10.476 52.527,10.976 53.527,10.976 54.527,10.976 55.527,10.976 52.725,11.978 56.196,12.027 52.744,13.149 56.174,13.234 56.454,14.236 52.299,14.327 53.299,14.327 54.299,14.327 55.299,14.327 56.954,14.736 52.799,14.827 53.799,14.827 54.799,14.827 55.799,14.827 52.262,15.942 53.262,15.942 54.262,15.942 55.262,15.942 56.35,15.976 52.762,16.442 53.762,16.442 54.762,16.442 55.762,16.442 56.85,16.476 52.674,18.5 52.174,19 56.674,19 57.674,19 52.674,19.5 57.174,19.5 56.674,20
RSD_MCU: J2.59 J5.7 | length 40.1
  Power1 w0.254: J2.59@84.874,42.65 87.963,42.65 88.592,42.021 88.592,30.947 89.067,30.472 110.19,30.472 J5.7@112.524,28.138
RST_MCU: J2.57 J4.2 | length 60.1
  Power1 w0.254: J2.57@84.874,41.85 87.54,41.85 88.039,41.351 88.039,12.649 88.187,12.5 105.302,12.5 J4.2@112.893,4.909
SD_EN: J2.77 R54.2 U11.8 | length 25.9
  Power1 w0.254: J2.77@84.874,49.85 87.881,49.85 89.891,51.859 v1(89.891,56.975) ; v1(90.174,59) 90.679,59.505 94.866,59.505 95.445,60.085 R54.2@95.645,60.085 ; R54.2@95.645,60.127 96.53,60.127 97.907,58.75 U11.8@101.774,58.75
  Power2 w0.254: v1(89.891,56.975) 89.891,57.648 89.66,57.879 89.66,58.486 v1(90.174,59)
SPI_CLK: R27.1 R46.1 U11.3 | length 24.9
  Power1 w0.254: R27.1@89.77,47.552 89.943,47.725 90.444,47.725 v1(90.801,48.081) ; R46.1@94.174,57.75 94.374,57.75 94.497,57.627 94.497,57.474 94.624,57.347 v1(94.624,57.278) ; v1(100.953,61.331) 101.022,61.331 101.103,61.25 U11.3@101.774,61.25
  Power2 w0.254: v1(90.801,48.081) 90.801,49.37 96.698,55.267 ; v1@94.755,57.278 v1(94.624,57.278) 96.634,55.267 96.698,55.267 ; v1(100.953,61.331) 100.904,61.38 100.335,61.38 100.238,61.477 98.702,61.477 97.674,60.449 97.674,56.243 96.698,55.267
SPI_CS: R28.1 R49.1 U11.6 | length 22.5
  Power1 w0.254: R28.1@89.774,48.5 89.874,48.5 90.703,49.329 v1(91.625,49.329) ; R49.1@95.674,61.75 96.597,61.75 v1(98.42,59.927) ; v1@98.469,59.878 98.537,59.878 98.665,59.75 U11.6@101.774,59.75
  Power2 w0.254: v1(91.625,49.329) 98.42,56.124 v1(98.42,59.927)
SPI_SIMO: R24.1 R47.1 U11.4 | length 31.6
  Power1 w0.254: R24.1@89.734,45.636 89.763,45.665 91.731,45.665 v1(91.76,45.693) ; R47.1@94.174,61.75 94.374,61.75 94.951,62.327 96.989,62.327 98.239,61.077 99.109,61.077 99.309,60.877 99.774,60.877 99.871,60.78 99.949,60.78 99.979,60.75 U11.4@101.774,60.75
  Ground2 w0.254: v1(91.76,45.693) 92.695,45.693 94.133,47.132 94.133,53.281 96.273,55.421 96.273,60.6 96.666,60.992 99.213,60.992 99.328,60.877 99.774,60.877 v1(99.822,60.829)
SPI_SOMI: R26.1 R48.1 U11.5 | length 26.3
  Power1 w0.254: R26.1@89.749,46.619 89.914,46.454 v1@94.449,46.454 ; R48.1@95.674,57.75 95.797,57.873 95.883,57.787 96.981,57.787 v1(97.017,57.823) ; v1(99.034,60.331) 99.102,60.331 99.186,60.248 U11.5@101.601,60.248
  Ground2 w0.254: v1(94.457,46.462) 94.457,46.503 94.758,46.804 94.758,50.021 94.776,50.038 94.776,53.281 98.174,56.679 98.174,56.831 97.23,57.775 97.066,57.775 v1(97.017,57.823) ; 98.174,56.683 98.247,56.757 99.006,57.516 99.006,60.304 v1(99.034,60.331)
String_PGND: C69.2 J3.2 L4.2 R23.1 T2.7 | length 43.6
  Power1 w1: 38.888,82.5 52.705,82.5 T2.7@58.552,76.653
  Power2 w1: 39.5,82.5 52.705,82.5 T2.7@58.552,76.653
  other v1: 27.648,72.199 29.451,72.255 21.9,72.394 22.9,72.394 23.9,72.394 24.9,72.394 18.171,72.6 19.648,72.699 27.148,72.699 28.951,72.755 22.4,72.894 23.4,72.894 24.4,72.894 25.4,72.894 17.671,73.1 19.148,73.199 27.648,73.199 29.451,73.255 18.171,73.6 19.648,73.699 27.148,73.699 28.951,73.755 21.9,73.894 22.9,73.894 23.9,73.894 24.9,73.894 17.671,74.1 19.148,74.199 27.648,74.199 29.451,74.255 38.217,74.368 22.4,74.394 23.4,74.394 24.4,74.394 25.4,74.394 37.297,74.449 39.057,74.498 18.171,74.6 19.648,74.699 27.148,74.699 28.951,74.755 36.603,74.958 39.783,74.99 38.403,75.014 37.604,75.079 17.671,75.1 19.148,75.199 27.648,75.199 39.034,75.211 29.451,75.255 37.031,75.571 18.171,75.6 19.648,75.699 27.148,75.699 28.951,75.755 39.597,75.821 36.176,75.965 17.671,76.1 19.148,76.199 27.648,76.199 29.451,76.255 36.676,76.465 18.171,76.6 39.807,76.596 19.648,76.699 27.148,76.699 28.951,76.755 36.176,76.965 17.671,77.1 19.148,77.199 27.648,77.199 36.805,77.218 29.451,77.255 39.597,77.339 18.171,77.6 19.648,77.699 27.148,77.699 28.951,77.755 37.241,77.783 38.176,77.965 39.176,77.965 17.671,78.1 19.148,78.199 27.648,78.199 29.451,78.255 18.171,78.6 19.648,78.699 27.148,78.699 28.951,78.755 17.671,79.1 19.148,79.199 27.648,79.199 29.451,79.255 18.171,79.6 19.648,79.699 27.148,79.699 28.951,79.755 17.671,80.1 19.148,80.199
SW1: U3.5 U7.1 | length 11.9
  Power2 w0.2: v2(32.174,32.5) 32.174,26.655 32.491,26.338 v1(32.491,20.764)
  other v1: 31.181,17.4 29.694,17.407 30.423,17.407 31.903,17.408 32.55,17.87 31.17,18.046 31.893,18.075 32.53,18.568 31.16,18.714 31.903,18.795 32.53,19.329 31.17,19.433 31.882,19.534 32.53,20.069 31.15,20.173 31.872,20.243 31.139,20.882 31.874,20.928 31.126,21.63
SW2: L1.1 U7.2
  other v1: 31.129,23.357 29.243,23.908 31.162,24.133 28.544,24.693 29.276,24.685 31.155,25.01 29.269,25.561 27.813,25.605 28.525,25.6 31.152,25.953 27.823,26.518 29.266,26.504 28.545,26.528 31.161,26.778 29.276,27.329 27.854,27.346 28.544,27.337 24.342,30.637 22.891,30.661 23.609,30.645 24.335,31.513 23.591,31.552 21.265,31.564 21.998,31.556 22.878,31.557 20.547,31.58 21.991,32.432 24.332,32.456 20.534,32.476 21.247,32.471 22.888,32.47 23.611,32.48 21.988,33.375 20.544,33.389 21.267,33.399
TX_PGA_IN: C80.2 R39.2 TP21.1 U11.13 | length 22.8
  Power1 w0.254: TP21.1@95.674,48 95.674,52.675 96.649,53.65 C80.2@96.674,53.65 96.972,53.352 97.464,53.352 97.674,53.143 97.674,50.51 97.869,50.314 102.059,50.314 103.483,51.738 R39.2@103.674,51.738 ; 97.452,53.352 99.143,55.043 101.466,55.043 102.35,55.927 102.417,55.927 102.424,55.934 U11.13@102.424,56.1
TX_PGA_OUT: R51.2 TP24.1 U11.14 | length 11.1
  Power1 w0.254: v1(98.03,49.429) 98.03,48.143 TP24.1@98.174,48 ; v1(98.527,52.797) 98.527,52.806 98.983,53.262 R51.2@99.174,53.262 99.364,53.262 100.644,54.542 101.763,54.542 102.917,55.695 102.917,56.093 U11.14@102.924,56.1
  Power2 w0.254: v1(98.03,49.429) 98.03,52.3 v1(98.527,52.797)
UART_RX: J2.76 J5.5 | length 43.3
  Power1 w0.254: J2.76@81.474,49.05 81.597,48.927 82.247,48.927 82.674,48.5 82.674,41.5 84.782,39.391 v1(86.354,39.391)
  Power2 w0.254: v1(86.354,39.391) 89.29,39.391 90.196,38.485 90.196,30.722 90.896,30.022 105.56,30.022 J5.5@107.444,28.138
UART_TX: J2.78 J5.6 | length 46.2
  Power1 w0.254: J2.78@81.474,49.85 81.597,49.727 82.434,49.727 83.132,49.029 83.132,41.708 84.84,40 v1(85.674,40)
  Power2 w0.254: v1(85.674,40) 89.789,40 91.015,38.774 91.015,31.233 91.247,31 107.122,31 J5.6@109.984,28.138
Vafe: C47.2 C48.2 C52.1 C96.2 C97.2 C98.2 C99.1 C100.1 C101.1 C113.1 C114.1 C115.1 D9.1 L2.2 R21.2 R50.2 U4.4 U4.5 U11.44 U11.45 | length 100.6
  Power1 w0.254: C47.2@73.739,23.574 74.163,23.997 74.702,23.997 74.79,24.085 v1(74.859,24.085) ; v1(101.816,70) R50.2@102.412,70 ; 103.174,64.643 103.924,63.893 U11.45@103.924,62.9 ; 103.674,64.9 103.674,64.643 104.424,63.893 U11.44@104.424,62.9 ; R21.2@108.551,43 108.678,43.126 108.678,44.886 108.826,45.035 113.15,45.035 v1(114.38,46.265) ; D9.1@110.674,66.5 D9.1@111.185,65.988
  Power1 w0.4: D9.1@111.185,65.988 111.246,66.049 v1(112.688,66.049)
  Power1 w0.6: v1(90,20) 122,20 127,25 v1(127,46.5)
  Ground1 w0.6: v1(74.859,24.085) 88.649,24.085 89,23.734 89,20.5 89.501,19.999 89.999,19.999 v1(90,20)
  Power2 w0.254: C52.1@109.83,45.002 111.91,45.002 113.516,46.608 C114.1@113.516,46.773
  other v1: 95.674,65 98.424,65.125 99.924,65.125 101.424,65.125 95.668,65.938
VCC-3V3: C57.2 C58.2 C59.2 C62.1 C63.1 C102.1 C103.1 C104.2 C105.1 C106.1 C107.2 D8.1 D13.1 FB1.1 FB2.1 FB3.1 J4.7 R22.2 R29.2 R46.2 R47.2 R48.2 R49.2 R55.1 R61.2 R62.2 R72.2 R74.2 R76.2 TP15.1 U6.5 U10.1 U11.2 U11.11 U11.30 | length 337.1
  Power1 w0.254: R61.2@91.483,79.262 R61.2@91.674,79.262 ; v1(92.16,55.618) R55.1@92.16,56.213 ; v1@94.167,63.8 v1(94.174,63.794) R47.2@94.174,63.25 ; v1(94.174,55.643) R46.2@94.174,56.25 ; v1(95.398,55.681) 95.399,55.682 95.399,56.127 95.522,56.25 R48.2@95.674,56.25 ; R49.2@95.674,63.25 95.69,63.266 v1(95.69,63.776) ; C104.2@98.67,61.9 98.852,62.081 99.318,62.081 v1(99.366,62.13) 99.435,62.13 99.55,62.015 100.043,62.015 C105.1@100.17,61.888 100.194,61.912 101.194,61.912 101.349,61.757 101.767,61.757 U11.2@101.774,61.75 ; C102.1@100.045,57.562 100.235,57.562 100.362,57.435 100.362,57.424 100.511,57.275 100.851,57.275 v1(100.876,57.25) U11.11@101.774,57.25 ; TP15.1@104.638,32.675 103.234,34.078 v1(101.682,34.078) 106,38.396 R22.2@106,39.4 ; U11.30@108.574,59.25 108.581,59.257 108.933,59.257 109.397,59.72 109.397,60.794 v1(110.102,61.5) 110.412,61.81 C103.1@110.412,62 ; v1(120.287,17.687) 120.813,18.213 C107.2@120.813,18.238
  Power1 w0.4: FB2.1@71.789,17.737 71.939,17.587 72.22,17.587 73.464,16.343 74.601,16.343 75.935,15.009 v1(75.935,13.804) ; R29.2@86.174,81.262 R76.2@88.174,81.262 89.483,81.262 R61.2@91.483,79.262 ; R61.2@91.674,79.262 R62.2@93.674,79.262 95.412,79.262 97.174,77.5 v1(97.174,70.5) ; D13.1@118.674,61.5 118.706,61.467 v1(120.066,61.467)
  Power1 w0.6: v1(64.657,46.931) 64.657,47.556 FB3.1@64.832,47.731 ; C106.1@92.674,53.7 v1(92.674,54.643)
  Power1 w0.8: v1(13,5.5) 12.5,6 12.5,24 14,25.5 FB1.1@14.8,25.5
  Ground1 w0.6: v1(74.291,43.363) 92.422,43.363 v1(92.449,43.336)
  Ground2 w0.4: 75.935,6 v1(75.935,13.804) ; 101.674,33.538 103.836,31.375 118.483,31.375 120.287,29.571 v1(120.287,17.687)
  Ground2 w0.6: v1(64.657,46.931) 65.249,46.339 70.335,46.339 73.311,43.363 v1(74.291,43.363) ; 89.141,53.5 89.141,45.019 90.803,43.357 v1@92.428,43.357 ; v1(92.449,43.336) 92.466,43.353 93.826,43.353 97.091,40.088 v1@97.091,35.385 ; 94.174,8 97.102,8 J4.7@100.139,4.963 ; 101.674,33.5 101.674,33.538 ; v1@101.674,34.07 v1(101.682,34.078)
  Ground2 w0.8: v1(13,5.5) 17.184,1.316 32.074,1.316 ; v1(29.674,3.716) 32.074,1.316 ; 101.674,33.5 98.668,30.494 94.94,30.494 94.174,29.728 94.174,8 92.174,6 75.935,6 75.935,2.762 74.49,1.316 32.074,1.316 ; 101.674,33.538 v1@101.674,34.07
  Power2 w0.254: v1(29.674,3.716) 29.674,11.384 32.131,13.841 R74.2@32.709,13.841 ; R72.2@40.593,41.757 40.644,41.706 40.644,41.291 41.435,40.5 46.484,40.5 48.237,42.254 57.927,42.254 62.605,46.931 v1(64.657,46.931) ; C62.1@98.499,36.113 C62.1@98.502,36.11 ; U10.1@120.269,16.9 120.278,16.909 120.278,17.678 v1(120.287,17.687)
  Power2 w0.4: v1(98.502,35.315) C62.1@98.502,36.11
  other v1: 97.08,35.374
VCC_5V: C36.2 C37.2 C38.2 C39.2 C40.2 C41.2 C42.2 C43.2 C54.1 C64.1 D5.1 D6.1 J2.48 J2.84 J2.98 J2.112 R5.1 R7.1 TP13.1 U6.1 U6.3 | length 205.7
  Power1 w0.254: D6.1@75.547,30.576 D6.1@75.843,30.28 ; v1(78.92,34.646) v1@78.922,34.648 ; J2.112@81.418,63.394 J2.112@81.474,63.45 ; J2.98@81.441,57.818 J2.98@81.474,57.85 ; J2.48@81.472,34.648 J2.48@81.474,34.65 ; v1(92.716,34.493) TP13.1@93.681,34.493
  Power1 w0.35: C37.2@42.027,41.218 42.227,41.418 42.227,41.908 42.263,41.943 v1(42.263,41.986)
  Power1 w0.4: C40.2@32.551,12.172 32.57,12.153 33.22,12.153 v1(33.239,12.135) ; v1(78.019,63.345) 78.048,63.345 v1@78.153,63.45 ; J2.112@81.368,63.45 J2.112@81.418,63.4
  Power1 w0.6: C41.2@31.344,12.172 C40.2@32.551,12.172 ; C37.2@42.027,41.218 42.027,39.72 42.322,39.425 46.599,39.425 48.674,41.5 53.58,41.5 v1(53.601,41.479) ; v1@78.153,63.45 J2.112@81.368,63.45 ; v1(78.554,57.785) 78.602,57.833 79.65,57.833 ; v1@78.922,34.648 J2.48@81.472,34.648 ; v1(78.964,52.256) 81.467,52.256 J2.84@81.474,52.25
  Ground2 w0.6: v1(33.239,12.135) 32.955,12.135 32.683,11.863 32.683,6.414 34.257,4.84 73.014,4.84 74.674,6.5 74.674,14.715 76.582,16.624 76.582,31.091 76.078,31.595 v1(75.249,31.595) ; v1(53.601,41.479) 53.622,41.5 73.674,41.5 75.778,39.395 75.778,34.345 v1(74.917,33.484) ; v1(75.222,32.494) 75.717,32.494 76.486,33.263 76.486,34.841 ; 76.486,52.256 v1(78.964,52.256) ; v1(78.019,63.345) 76.081,61.407 76.081,57.785 ; v1(78.554,57.785) 76.081,57.785 ; v1(78.92,34.646) 78.684,34.882 76.527,34.882 76.486,34.841 ; v1(94.174,39) 90.976,42.198 76.486,42.198 ; 76.081,57.785 76.081,52.662 76.432,52.311 76.486,52.311 76.486,42.198 ; 76.486,34.841 76.486,42.198
  Power2 w0.254: v1(42.263,41.986) v1@42.285,42.008 ; C39.2@42.285,42.473 C39.2@42.307,42.495 ; v1@74.674,33.5 74.901,33.5 v1(74.917,33.484) ; C64.1@92.382,36.15 92.519,36.013 92.634,35.898 92.634,34.643 92.716,34.562 v1(92.716,34.493) ; U6.3@94.174,38.086 94.347,37.913 U6.3@94.381,37.913
  Power2 w0.35: v1(33.239,12.135) 33.247,12.143 33.805,12.143 C42.2@33.813,12.151 33.826,12.138 34.463,12.138 34.501,12.176 34.941,12.176 35.115,12.351 R7.1@35.229,12.351 ; R5.1@41.997,43.824 41.997,43.51 42.236,43.27 42.282,43.27 42.307,43.245 C39.2@42.307,42.495 ; v1@42.285,42.008 C39.2@42.285,42.473
  Power2 w0.4: U6.1@94.381,36.013 94.481,36.113 95.231,36.113 95.465,36.347 95.465,37.579 95.231,37.813 94.481,37.813 U6.3@94.381,37.913
  Power2 w0.6: C64.1@92.519,36.013 U6.1@94.381,36.013 ; U6.3@94.174,38.086 v1(94.174,39)
VIN+: C3.2 C5.2 C6.2 C7.2 C8.2 C9.2 C10.2 C11.2 C12.2 C13.2 C14.2 C21.2 C23.2 C25.2 C27.2 C29.2 C55.2 C56.2 C111.2 J1.1 R40.2 U3.7 U5.2 U5.3 | length 142.6
  Power1 w0.254: 43.815,30.185 v1(43.815,31.589) ; v1(62.174,42.5) 64.077,42.5 R40.2@64.097,42.48
  Ground1 w0.254: v1(43.815,31.589) 43.825,31.599 43.825,37.227 v1(43.834,37.237)
  Power2 w0.254: v1(43.834,37.237) 45.894,37.237 49.399,40.742 60.416,40.742 v1(62.174,42.5)
  Power2 w0.4: C111.2@112.552,34.157 112.635,34.24 U5.2@112.635,36.125
  Power2 w0.8: J1.1@47.355,12.608 47.355,4.819 48.067,4.107 76.988,4.107 77.928,3.167 116.196,3.167 117.5,4.471 117.5,29.276 116.671,30.105 113.487,30.105 111.847,31.745 C56.2@111.847,32.22
  other v1: 46.02,10.502 47.02,10.502 48.02,10.502 49.02,10.502 50.02,10.502 45.52,11.002 46.52,11.002 48.52,11.002 49.52,11.002 46.617,12.293 45.633,12.314 49.597,12.413 46.641,13.21 45.657,13.225 49.597,13.312 45.918,14.264 46.918,14.264 47.918,14.264 48.918,14.264 49.918,14.264 46.418,14.764 47.418,14.764 48.418,14.764 49.418,14.764 45.93,15.542 46.93,15.542 47.93,15.542 48.93,15.542 49.93,15.542 46.43,16.042 47.43,16.042 48.43,16.042 49.43,16.042 45.381,18.783 44.27,19.442 45.381,19.783 44.27,20.442 45.381,20.783 44.27,21.442 44.936,22.056 38.283,22.339 44.282,22.73 38.954,22.934 44.972,23.284 38.343,23.384 38.963,23.646 37.899,25.087 38.689,25.096 43.985,25.171 39.027,25.713 43.985,26.24 39.043,26.528 41.129,28.439 38.997,28.476 38.174,28.5 39.941,28.488
VOUT: C2.2 C4.2 C15.2 C16.2 C17.2 C18.2 C19.2 C20.2 C22.2 C24.2 C26.2 C28.2 C60.2 C61.2 J3.1 Q1.5 Q1.6 Q1.7 Q1.8 Q1.9@46.023,62.587 Q2.3 R6.1 R41.2 U2.7 | length 61
  Power1 w0.254: 49.243,66.93 60.743,66.93 62.674,65 73.674,65 75.674,63 75.674,45.649 75.036,45.011 74.192,45.011 R41.2@74.004,44.823
  Power1 w0.4: 49.174,66.5 60.174,66.5 60.834,65.84 Q2.3@60.834,64.168
  other v1: 29.108,48.275 24.009,48.292 23.509,48.792 29.608,48.775 29.108,49.275 24.009,49.292 29.608,49.775 23.509,49.792 24.009,50.292 29.108,50.275 29.608,50.775 23.509,50.792 29.108,51.275 24.009,51.292 25.013,51.451 26.013,51.451 27.013,51.451 28.013,51.451 25.513,51.951 26.513,51.951 27.513,51.951 24.999,52.685 25.999,52.685 26.999,52.685 27.999,52.685 25.499,53.185 26.499,53.185 27.499,53.185 25.038,53.77 26.038,53.77 27.038,53.77 28.038,53.77 25.538,54.27 26.538,54.27 27.538,54.27 39.464,58.698 42.402,58.815 45.398,58.85 47.658,59.589 44.637,59.618 46.079,59.599 42.989,59.648 37.046,59.795 38.704,59.824 40.057,59.873 41.744,59.854 46.285,60.729 45.1,60.751 47.687,60.762 45.785,61.229 47.187,61.262 45.1,61.751 46.285,61.729 47.687,61.762 45.785,62.229 47.187,62.262 46.285,62.729 45.1,62.751 47.687,62.762 45.785,63.229 47.187,63.262 46.285,63.729 45.1,63.751 47.687,63.762 45.785,64.229 47.187,64.262 43.878,74.292 44.878,74.292 45.878,74.292 43.07,74.357 44.378,74.792 45.378,74.792 42.57,74.857 46.57,74.857 43.07,75.357 47.07,75.357 42.57,75.857 46.57,75.857 43.07,76.357 47.07,76.357 42.57,76.857 46.57,76.857 43.07,77.357 47.07,77.357 42.57,77.857 46.57,77.857 43.07,78.357 44.07,78.357 45.07,78.357 46.07,78.357 43.57,78.857 44.57,78.857 45.57,78.857
pads on no net: H1.1 H2.1 H3.1 H4.1 H5.0 H6.0 H7.0 H8.0 J2.1 J2.2 J2.3 J2.4 J2.5 J2.6 J2.8 J2.9 J2.11 J2.13 J2.15 J2.16 J2.17 J2.18 J2.21 J2.25 J2.27 J2.28 J2.30 J2.31 J2.32 J2.33 J2.34 J2.36 J2.37 J2.39 J2.40 J2.41 J2.42 J2.43 J2.44 J2.45 J2.58 J2.60 J2.62 J2.64 J2.66 J2.74 J2.79 J2.80 J2.81 J2.82 J2.86 J2.87 J2.88 J2.89 J2.90 J2.91 J2.92 J2.93 J2.94 J2.95 J2.96 J2.99 J2.100 J2.101 J2.102 J2.103 J2.104 J2.105 J2.106 J2.107 J2.108 J2.109 J2.110 J2.113 J2.114 J2.115 J2.116 J2.117 J2.118 J2.119 J2.120 J2.181 J2.182 J2.185 J2.186 J4.1 J4.3 J4.4 J4.5 J4.6 J5.2 J5.3 J5.4 J5.8 L1.3 L4.3 LBL1.0 Q1.9@45.338,61.257 Q1.9@45.338,62.587 Q1.9@45.338,63.917 Q1.9@46.353,62.587 Q1.9@46.488,61.257 Q1.9@46.488,62.587 Q1.9@46.488,63.917 Q1.9@47.638,61.257 Q1.9@47.638,62.587 Q1.9@47.638,63.917 Q1.9@47.933,60.214 Q1.9@47.933,64.959 T1.1 T1.3 T2.5 T2.6 T2.9 U2.1 U2.2 U3.1 U3.2 U11.10 U11.31 U11.32 U11.33 U11.36 U11.37 U11.47 U11.48 U11.49@103.804,58.13 U11.49@103.804,59.5 U11.49@103.804,60.87 U11.49@105.174,58.13 U11.49@105.174,59.5 U11.49@105.174,60.87 U11.49@106.544,58.13 U11.49@106.544,59.5 U11.49@106.544,60.87
copper on no net:
  other v3: 19.174,10 62.174,10 19.174,53 62.174,53

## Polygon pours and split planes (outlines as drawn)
PGND on Power1 "NONET_L-01_P-001" (solid, remove dead copper, pour order 77): 48.522,18 50.674,18 51.674,19 51.674,22 51.68,22 52.361,22.68 57.854,22.68 58.174,23 58.174,27 53.174,32 48.174,37 36.521,37 36.174,36.652 36.174,31.421 43.253,31.421 45.174,29.5 45.174,28 46.674,26.5 46.674,24.5 47.674,23.5 47.674,21.498 48.177,20.994 48.177,18.344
